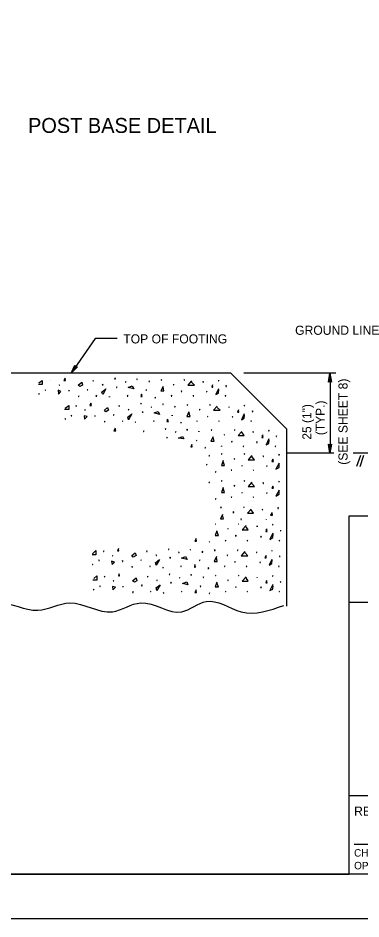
# Model space of a CAD drawing. Extents: x 637580 to 641008, y 294594 to 295782.
# Drawn here: x 638095.4 to 638210.3, y 294593.6 to 294895.4 of the extents above; entities that cross this region are included whole.
import ezdxf

# ---------------------------------------------------------------- set-up
doc = ezdxf.new("R2010")
doc.units = 0
for name, color, linetype in [('1', 7, 'Continuous'), ('2', 7, 'Continuous'), ('3', 7, 'Continuous'), ('PLT-BNDY', 7, 'Continuous')]:
    doc.layers.add(name, color=color, linetype=linetype)

# ---------------------------------------------------------------- blocks, each defined once
blk = doc.blocks.new('RARROW')
at = {"layer": '3'}
blk.add_lwpolyline([(-2.2695, 0.285), (-2.184875, 0.12075), (0, 0), (-2.2695, 0.285), (-2.38575, 0.384625), (0, 0), (-2.183125, -0.108), (-2.262875, -0.2705), (0, 0), (-2.38575, -0.379125), (-2.262875, -0.2705)], dxfattribs=at)

msp = doc.modelspace()

# ---------------------------------------------------------------- linework, layer by layer
at = {"layer": '1'}
for p, q in [((638210.18, 294748.88), (638208.8, 294745.13)), ((638211.18, 294748.88), (638209.93, 294745)), ((638206.31, 294608.63), (638206.31, 294728.63)), ((638206.31, 294728.63), (638406.31, 294728.63)), ((638406.31, 294699.63), (638206.31, 294699.63)), ((638206.31, 294635), (638406.31, 294635)), ((638207.99, 294618.68), (638281.87, 294618.68)), ((638406.31, 294608.63), (637620.31, 294608.63)), ((637620.31, 294608.63), (638206.31, 294608.63))]:
    msp.add_line(p, q, dxfattribs=at)
at = {"layer": '2'}
for p, q in [((638121.3, 294788), (638113.25, 294776.38)), ((638128.7, 294788), (638121.3, 294788)), ((638166.68, 294776.38), (637860.68, 294776.38)), ((638166.68, 294776.38), (638185.3, 294757.75)), ((638201.93, 294776.38), (638171.05, 294776.38)), ((638199.93, 294776.38), (638199.93, 294749.63)), ((638185.3, 294757.75), (638185.3, 294698.38)), ((638201.18, 294749.63), (638185.3, 294749.63)), ((638232.3, 294749.63), (638207.68, 294749.63))]:
    msp.add_line(p, q, dxfattribs=at)
for points in [[(638102.43, 294773.13), (638103.55, 294774), (638103.55, 294772.63), (638102.3, 294772.63)], [(638106.18, 294773.88), (638106.18, 294773.88), (638106.18, 294773.88), (638106.18, 294773.88)], [(638109.18, 294772.5), (638109.18, 294772.38), (638109.3, 294772.38), (638109.18, 294772.5)], [(638111.18, 294774.75), (638110.8, 294774), (638111.3, 294774), (638111.18, 294774.75)], [(638115.55, 294772.38), (638116.8, 294773.38), (638117.05, 294772.38), (638116.18, 294772), (638115.55, 294772.38)], [(638120.68, 294773.88), (638120.55, 294773.88), (638120.68, 294773.88), (638120.68, 294773.88)], [(638123.8, 294772.75), (638123.68, 294772.5), (638123.93, 294772.5), (638123.8, 294772.63)], [(638128.05, 294774.75), (638127.8, 294774.5), (638128.05, 294774.5), (638128.05, 294774.63)], [(638131.55, 294773.63), (638131.43, 294773.38), (638131.55, 294773.38), (638131.55, 294773.63)], [(638135.18, 294774.5), (638135.18, 294774.25), (638135.3, 294774.25), (638135.18, 294774.5)], [(638139.43, 294773.88), (638139.3, 294773.63), (638139.43, 294773.63), (638139.43, 294773.88)], [(638143.55, 294774.25), (638143.43, 294774.13), (638143.55, 294774.13), (638143.55, 294774.25)], [(638147.55, 294772.75), (638147.55, 294772.5), (638147.68, 294772.5), (638147.55, 294772.63)], [(638151.05, 294774.25), (638151.05, 294774.13), (638151.18, 294774.13), (638151.05, 294774.25)], [(638153.55, 294773.88), (638152.3, 294772.38), (638154.55, 294772.38), (638153.55, 294773.38)], [(638157.43, 294773.63), (638157.3, 294773.38), (638157.55, 294773.38), (638157.43, 294773.63)], [(638160.55, 294772.5), (638160.3, 294771.75), (638160.68, 294771.75), (638160.55, 294772.38)], [(638162.55, 294774.13), (638162.55, 294773.88), (638162.68, 294773.88), (638162.55, 294774)], [(638102.43, 294769.63), (638102.43, 294769.38), (638102.55, 294769.38), (638102.43, 294769.63)], [(638104.55, 294770.88), (638104.55, 294770.75), (638104.68, 294770.75), (638104.55, 294770.88)], [(638108.93, 294770.75), (638109.05, 294769.38), (638109.8, 294770.25), (638108.93, 294770.75)], [(638112.55, 294770.75), (638112.43, 294770.5), (638112.55, 294770.5), (638112.55, 294770.75)], [(638118.68, 294771), (638118.55, 294770.88), (638118.8, 294770.88), (638118.68, 294771)], [(638123.68, 294770.13), (638124.8, 294771.13), (638123.8, 294769.25), (638123.43, 294770.13)], [(638128.55, 294771.88), (638128.43, 294771.63), (638128.55, 294771.63), (638128.55, 294771.88)], [(638134.18, 294771.13), (638132.3, 294771.63), (638133.68, 294772.13), (638134.18, 294771.13)], [(638138.43, 294770.88), (638138.3, 294770.75), (638138.43, 294770.75), (638138.43, 294770.88)], [(638144.05, 294772), (638143.3, 294770.5), (638144.3, 294770.5), (638144.05, 294771.88)], [(638150.18, 294770.5), (638150.05, 294770.25), (638150.3, 294770.25), (638150.18, 294770.5)], [(638158.68, 294770.38), (638158.55, 294770.13), (638158.68, 294770.13), (638158.68, 294770.25)], [(638162.55, 294771.13), (638161.68, 294769.25), (638162.55, 294769.75), (638162.68, 294770.88)], [(638165.18, 294772.25), (638165.05, 294772), (638165.3, 294772), (638165.18, 294772.25)], [(638115.8, 294768.88), (638115.68, 294768.63), (638115.8, 294768.63), (638115.8, 294768.75)], [(638121.68, 294769), (638121.55, 294768.75), (638121.8, 294768.75), (638121.68, 294768.88)], [(638126.05, 294768.63), (638126.05, 294768.38), (638126.05, 294768.38), (638126.05, 294768.63)], [(638132.18, 294769), (638132.05, 294768.75), (638132.18, 294768.75), (638132.18, 294768.88)], [(638136.8, 294769.38), (638136.55, 294768.63), (638137.05, 294768.63), (638136.8, 294769.38)], [(638141.43, 294768.38), (638141.3, 294768.13), (638141.43, 294768.13), (638141.43, 294768.38)], [(638146.8, 294769), (638146.68, 294768.75), (638146.93, 294768.75), (638146.8, 294768.88)], [(638154.05, 294769), (638154.05, 294768.75), (638154.18, 294768.75), (638154.05, 294768.88)], [(638164.93, 294769), (638164.8, 294768.75), (638164.93, 294768.75), (638164.93, 294768.88)], [(638111.18, 294764.75), (638112.43, 294765.63), (638112.43, 294764.25), (638111.05, 294764.25)], [(638114.93, 294765.63), (638114.8, 294765.38), (638115.05, 294765.38), (638114.93, 294765.5)], [(638117.93, 294764.25), (638117.8, 294764), (638117.93, 294764), (638117.93, 294764.13)], [(638119.8, 294766.38), (638119.55, 294765.63), (638120.05, 294765.63), (638119.8, 294766.38)], [(638124.43, 294764), (638125.43, 294764.88), (638125.8, 294764), (638124.8, 294763.5), (638124.43, 294764)], [(638129.3, 294765.63), (638129.18, 294765.38), (638129.43, 294765.38), (638129.3, 294765.5)], [(638132.43, 294764.38), (638132.43, 294764.13), (638132.55, 294764.13), (638132.43, 294764.38)], [(638136.68, 294766.38), (638136.55, 294766.13), (638136.68, 294766.13), (638136.68, 294766.38)], [(638137.18, 294763.5), (638137.05, 294763.38), (638137.3, 294763.38), (638137.18, 294763.38)], [(638140.18, 294765.13), (638140.05, 294765), (638140.18, 294765), (638140.18, 294765.13)], [(638142.8, 294762.63), (638141.05, 294763.13), (638142.43, 294763.63), (638142.8, 294762.63)], [(638144.05, 294766.13), (638143.93, 294765.88), (638144.05, 294765.88), (638144.05, 294766.13)], [(638148.05, 294765.38), (638147.8, 294765.13), (638148.05, 294765.13), (638148.05, 294765.38)], [(638152.68, 294763.5), (638151.93, 294761.88), (638153.05, 294761.88), (638152.68, 294763.38)], [(638152.18, 294765.88), (638152.05, 294765.75), (638152.18, 294765.75), (638152.18, 294765.88)], [(638156.3, 294764.38), (638156.18, 294764.13), (638156.3, 294764.13), (638156.3, 294764.38)], [(638159.8, 294765.88), (638159.68, 294765.75), (638159.8, 294765.75), (638159.8, 294765.88)], [(638162.18, 294765.38), (638160.93, 294764), (638163.18, 294764), (638162.18, 294764.88)], [(638166.05, 294765.13), (638166.05, 294765), (638166.18, 294765), (638166.05, 294765.13)], [(638169.3, 294764.13), (638168.93, 294763.38), (638169.43, 294763.38), (638169.3, 294764)], [(638171.3, 294765.75), (638171.18, 294765.5), (638171.3, 294765.5), (638171.3, 294765.75)], [(638173.93, 294763.75), (638173.93, 294763.5), (638174.05, 294763.5), (638173.93, 294763.75)], [(638111.18, 294761.25), (638111.18, 294761), (638111.3, 294761), (638111.18, 294761.25)], [(638113.3, 294762.38), (638113.3, 294762.13), (638113.43, 294762.13), (638113.3, 294762.38)], [(638117.55, 294762.13), (638117.68, 294761), (638118.55, 294761.88), (638117.55, 294762.13)], [(638121.18, 294762.25), (638121.18, 294762), (638121.3, 294762), (638121.18, 294762.13)], [(638127.55, 294762.63), (638127.43, 294762.38), (638127.55, 294762.38), (638127.55, 294762.63)], [(638130.43, 294760.5), (638130.43, 294760.38), (638130.55, 294760.38), (638130.43, 294760.5)], [(638132.3, 294761.75), (638133.55, 294762.75), (638132.43, 294760.75), (638132.18, 294761.75)], [(638140.93, 294760.5), (638140.8, 294760.38), (638141.05, 294760.38), (638140.93, 294760.5)], [(638145.55, 294761), (638145.3, 294760.25), (638145.8, 294760.25), (638145.55, 294760.88)], [(638147.05, 294762.38), (638147.05, 294762.13), (638147.05, 294762.13), (638147.05, 294762.38)], [(638155.43, 294760.5), (638155.3, 294760.38), (638155.43, 294760.38), (638155.43, 294760.5)], [(638158.93, 294762), (638158.93, 294761.88), (638159.05, 294761.88), (638158.93, 294762)], [(638162.8, 294760.5), (638162.68, 294760.38), (638162.8, 294760.38), (638162.8, 294760.5)], [(638167.3, 294761.88), (638167.18, 294761.75), (638167.43, 294761.75), (638167.3, 294761.88)], [(638171.18, 294762.75), (638170.3, 294760.75), (638171.18, 294761.38), (638171.3, 294762.38)], [(638173.55, 294760.5), (638173.43, 294760.38), (638173.68, 294760.38), (638173.55, 294760.5)], [(638124.55, 294760.38), (638124.43, 294760.13), (638124.55, 294760.13), (638124.55, 294760.38)], [(638127.93, 294758), (638127.55, 294757.13), (638128.18, 294757.13), (638127.93, 294757.88)], [(638134.8, 294760.13), (638134.68, 294760), (638134.8, 294760), (638134.8, 294760.13)], [(638144.8, 294757.88), (638144.68, 294757.63), (638144.93, 294757.63), (638144.8, 294757.75)], [(638150.05, 294760), (638149.93, 294759.75), (638150.05, 294759.75), (638150.05, 294760)], [(638152.05, 294757.63), (638151.93, 294757.38), (638152.18, 294757.38), (638152.05, 294757.63)], [(638160.3, 294757.5), (638160.18, 294757.38), (638160.3, 294757.38), (638160.3, 294757.38)], [(638167.93, 294757.5), (638167.93, 294757.38), (638168.05, 294757.38), (638167.93, 294757.38)], [(638179.43, 294757.38), (638179.3, 294757.13), (638179.55, 294757.13), (638179.43, 294757.38)], [(638137.55, 294757.13), (638137.43, 294756.88), (638137.55, 294756.88), (638137.55, 294757.13)], [(638145.43, 294755), (638145.3, 294754.75), (638145.43, 294754.75), (638145.43, 294755)], [(638148.3, 294756.88), (638148.18, 294756.63), (638148.3, 294756.63), (638148.3, 294756.75)], [(638150.93, 294754.38), (638149.18, 294754.63), (638150.55, 294755.25), (638150.93, 294754.38)], [(638156.05, 294757), (638156.05, 294756.75), (638156.05, 294756.75), (638156.05, 294756.88)], [(638160.8, 294755.13), (638160.05, 294753.63), (638161.18, 294753.63), (638160.8, 294755)], [(638164.43, 294755.88), (638164.43, 294755.75), (638164.55, 294755.75), (638164.43, 294755.88)], [(638170.43, 294756.88), (638169.18, 294755.5), (638171.18, 294755.5), (638170.43, 294756.63)], [(638174.18, 294756.88), (638174.05, 294756.63), (638174.3, 294756.63), (638174.18, 294756.75)], [(638177.3, 294755.75), (638177.05, 294754.88), (638177.55, 294754.88), (638177.3, 294755.63)], [(638179.43, 294754.38), (638178.55, 294752.38), (638179.43, 294752.88), (638179.55, 294754)], [(638182.05, 294755.38), (638181.93, 294755.25), (638182.05, 294755.25), (638182.05, 294755.38)], [(638153.68, 294752.5), (638153.3, 294751.75), (638153.8, 294751.75), (638153.68, 294752.5)], [(638155.18, 294754), (638155.18, 294753.88), (638155.3, 294753.88), (638155.18, 294754)], [(638158.18, 294751.5), (638158.05, 294751.38), (638158.18, 294751.38), (638158.18, 294751.5)], [(638163.55, 294752.13), (638163.55, 294751.88), (638163.55, 294751.88), (638163.55, 294752)], [(638167.05, 294753.63), (638166.93, 294753.38), (638167.18, 294753.38), (638167.05, 294753.63)], [(638170.93, 294752.13), (638170.8, 294751.88), (638170.93, 294751.88), (638170.93, 294752)], [(638175.55, 294753.5), (638175.3, 294753.25), (638175.55, 294753.25), (638175.55, 294753.38)], [(638181.68, 294752.13), (638181.55, 294751.88), (638181.68, 294751.88), (638181.68, 294752)], [(638159.55, 294748.88), (638159.3, 294748.75), (638159.55, 294748.75), (638159.55, 294748.88)], [(638163.68, 294749.5), (638163.55, 294749.25), (638163.68, 294749.25), (638163.68, 294749.5)], [(638171.3, 294749.5), (638171.18, 294749.25), (638171.3, 294749.25), (638171.3, 294749.5)], [(638173.8, 294748.88), (638172.55, 294747.38), (638174.68, 294747.38), (638173.8, 294748.5)], [(638177.55, 294748.75), (638177.55, 294748.5), (638177.68, 294748.5), (638177.55, 294748.75)], [(638182.93, 294749.25), (638182.8, 294749), (638182.93, 294749), (638182.93, 294749.25)], [(638158.68, 294746), (638158.55, 294745.75), (638158.68, 294745.75), (638158.68, 294745.88)], [(638164.18, 294747.13), (638163.55, 294745.5), (638164.55, 294745.5), (638164.18, 294746.88)], [(638167.93, 294747.88), (638167.8, 294747.63), (638167.93, 294747.63), (638167.93, 294747.88)], [(638170.43, 294745.5), (638170.43, 294745.38), (638170.55, 294745.38), (638170.43, 294745.5)], [(638178.8, 294745.38), (638178.68, 294745.25), (638178.93, 294745.25), (638178.8, 294745.38)], [(638180.8, 294747.63), (638180.43, 294746.88), (638181.05, 294746.88), (638180.8, 294747.63)], [(638182.93, 294746.25), (638181.8, 294744.25), (638182.93, 294744.88), (638182.93, 294746)], [(638161.68, 294743.5), (638161.55, 294743.25), (638161.68, 294743.25), (638161.68, 294743.5)], [(638166.93, 294744), (638166.8, 294743.88), (638167.05, 294743.88), (638166.93, 294743.88)], [(638174.3, 294744), (638174.18, 294743.88), (638174.3, 294743.88), (638174.3, 294743.88)], [(638159.55, 294740), (638159.3, 294739.75), (638159.55, 294739.75), (638159.55, 294739.88)], [(638163.68, 294740.5), (638163.55, 294740.25), (638163.68, 294740.25), (638163.68, 294740.5)], [(638171.3, 294740.5), (638171.18, 294740.25), (638171.3, 294740.25), (638171.3, 294740.5)], [(638173.8, 294739.88), (638172.55, 294738.5), (638174.68, 294738.5), (638173.8, 294739.5)], [(638177.55, 294739.75), (638177.55, 294739.5), (638177.68, 294739.5), (638177.55, 294739.75)], [(638182.93, 294740.25), (638182.8, 294740), (638182.93, 294740), (638182.93, 294740.25)], [(638164.18, 294738.13), (638163.55, 294736.5), (638164.55, 294736.5), (638164.18, 294737.88)], [(638167.93, 294738.88), (638167.8, 294738.63), (638167.93, 294738.63), (638167.93, 294738.88)], [(638170.43, 294736.5), (638170.43, 294736.38), (638170.55, 294736.38), (638170.43, 294736.5)], [(638178.8, 294736.38), (638178.68, 294736.25), (638178.93, 294736.25), (638178.8, 294736.38)], [(638180.8, 294738.63), (638180.43, 294737.88), (638181.05, 294737.88), (638180.8, 294738.63)], [(638182.93, 294737.25), (638181.8, 294735.25), (638182.93, 294735.88), (638182.93, 294737)], [(638161.68, 294734.5), (638161.55, 294734.25), (638161.68, 294734.25), (638161.68, 294734.5)], [(638166.93, 294735), (638166.8, 294734.88), (638167.05, 294734.88), (638166.93, 294735)], [(638174.3, 294735), (638174.18, 294734.88), (638174.3, 294734.88), (638174.3, 294735)], [(638163.43, 294731.63), (638163.3, 294731.38), (638163.55, 294731.38), (638163.43, 294731.5)], [(638171.05, 294731.63), (638171.05, 294731.38), (638171.05, 294731.38), (638171.05, 294731.5)], [(638173.55, 294730.88), (638172.3, 294729.5), (638174.3, 294729.5), (638173.55, 294730.63)], [(638177.3, 294730.88), (638177.18, 294730.63), (638177.3, 294730.63), (638177.3, 294730.75)], [(638182.55, 294731.38), (638182.43, 294731.13), (638182.68, 294731.13), (638182.55, 294731.38)], [(638163.93, 294729.13), (638163.3, 294727.63), (638164.3, 294727.63), (638163.93, 294729)], [(638167.68, 294730), (638167.43, 294729.75), (638167.68, 294729.75), (638167.68, 294730)], [(638170.18, 294727.63), (638170.05, 294727.38), (638170.3, 294727.38), (638170.18, 294727.63)], [(638178.55, 294727.5), (638178.55, 294727.38), (638178.55, 294727.38), (638178.55, 294727.38)], [(638180.55, 294729.75), (638180.05, 294728.88), (638180.68, 294728.88), (638180.55, 294729.63)], [(638161.68, 294725.88), (638161.55, 294725.88), (638161.68, 294725.88), (638161.68, 294725.88)], [(638165.8, 294724.38), (638165.68, 294724.25), (638165.8, 294724.25), (638165.8, 294724.38)], [(638169.3, 294725.88), (638169.3, 294725.88), (638169.43, 294725.88), (638169.3, 294725.88)], [(638171.8, 294725.38), (638170.55, 294724), (638172.55, 294724), (638171.8, 294725)], [(638175.55, 294725.25), (638175.55, 294725), (638175.55, 294725), (638175.55, 294725.25)], [(638178.68, 294724.25), (638178.43, 294723.38), (638178.93, 294723.38), (638178.68, 294724.13)], [(638180.8, 294725.88), (638180.68, 294725.63), (638180.8, 294725.63), (638180.8, 294725.75)], [(638162.05, 294723.63), (638161.43, 294722), (638162.55, 294722), (638162.05, 294723.5)], [(638168.43, 294722.13), (638168.3, 294721.88), (638168.55, 294721.88), (638168.43, 294722.13)], [(638176.8, 294721.88), (638176.68, 294721.63), (638176.93, 294721.63), (638176.8, 294721.88)], [(638180.8, 294722.88), (638179.8, 294720.75), (638180.8, 294721.38), (638180.93, 294722.5)], [(638183.3, 294723.88), (638183.3, 294723.63), (638183.43, 294723.63), (638183.3, 294723.75)], [(638155.05, 294721), (638154.68, 294720.13), (638155.18, 294720.13), (638155.05, 294721)], [(638159.55, 294720), (638159.43, 294719.88), (638159.55, 294719.88), (638159.55, 294719.88)], [(638164.93, 294720.5), (638164.93, 294720.25), (638165.05, 294720.25), (638164.93, 294720.5)], [(638172.3, 294720.5), (638172.18, 294720.25), (638172.3, 294720.25), (638172.3, 294720.5)], [(638183.05, 294720.5), (638182.93, 294720.25), (638183.05, 294720.25), (638183.05, 294720.5)], [(638120.43, 294715.88), (638121.55, 294717), (638121.55, 294715.63), (638120.3, 294715.63)], [(638124.18, 294716.88), (638124.05, 294716.75), (638124.18, 294716.75), (638124.18, 294716.88)], [(638127.18, 294715.38), (638127.05, 294715.25), (638127.18, 294715.25), (638127.18, 294715.38)], [(638129.05, 294717.75), (638128.8, 294716.88), (638129.18, 294716.88), (638129.05, 294717.63)], [(638133.55, 294715.38), (638134.68, 294716.25), (638135.05, 294715.38), (638134.05, 294714.75), (638133.55, 294715.38)], [(638138.55, 294716.88), (638138.43, 294716.75), (638138.68, 294716.75), (638138.55, 294716.88)], [(638141.68, 294715.63), (638141.68, 294715.38), (638141.8, 294715.38), (638141.68, 294715.63)], [(638145.93, 294717.63), (638145.8, 294717.38), (638145.93, 294717.38), (638145.93, 294717.5)], [(638149.43, 294716.63), (638149.18, 294716.38), (638149.43, 294716.38), (638149.43, 294716.5)], [(638153.05, 294717.38), (638153.05, 294717.25), (638153.18, 294717.25), (638153.05, 294717.38)], [(638157.3, 294716.75), (638157.05, 294716.5), (638157.3, 294716.5), (638157.3, 294716.75)], [(638161.43, 294717.25), (638161.18, 294717), (638161.43, 294717), (638161.43, 294717.25)], [(638165.55, 294715.63), (638165.43, 294715.38), (638165.55, 294715.38), (638165.55, 294715.63)], [(638169.05, 294717.25), (638168.93, 294717), (638169.05, 294717), (638169.05, 294717.25)], [(638171.43, 294716.75), (638170.18, 294715.25), (638172.43, 294715.25), (638171.43, 294716.38)], [(638175.3, 294716.63), (638175.3, 294716.38), (638175.43, 294716.38), (638175.3, 294716.5)], [(638178.55, 294715.38), (638178.05, 294714.63), (638178.55, 294714.63), (638178.55, 294715.38)], [(638180.55, 294717), (638180.43, 294716.88), (638180.55, 294716.88), (638180.55, 294717)], [(638183.05, 294715.25), (638183.05, 294715), (638183.18, 294715), (638183.05, 294715.13)], [(638120.43, 294712.5), (638120.43, 294712.38), (638120.55, 294712.38), (638120.43, 294712.38)], [(638122.55, 294713.88), (638122.55, 294713.63), (638122.68, 294713.63), (638122.55, 294713.75)], [(638126.8, 294713.5), (638126.93, 294712.38), (638127.8, 294713.13), (638126.8, 294713.5)], [(638130.43, 294713.63), (638130.43, 294713.38), (638130.55, 294713.38), (638130.43, 294713.63)], [(638136.55, 294713.88), (638136.55, 294713.75), (638136.68, 294713.75), (638136.55, 294713.88)], [(638141.55, 294713), (638142.8, 294714), (638141.68, 294712.13), (638141.43, 294713)], [(638146.43, 294714.75), (638146.3, 294714.5), (638146.55, 294714.5), (638146.43, 294714.75)], [(638152.05, 294714), (638150.18, 294714.5), (638151.55, 294715), (638152.05, 294714)], [(638154.68, 294712.38), (638154.55, 294711.5), (638154.93, 294711.5), (638154.68, 294712.25)], [(638156.3, 294713.88), (638156.18, 294713.63), (638156.3, 294713.63), (638156.3, 294713.75)], [(638161.93, 294715), (638161.18, 294713.38), (638162.18, 294713.38), (638161.93, 294714.75)], [(638168.05, 294713.38), (638168.05, 294713.13), (638168.18, 294713.13), (638168.05, 294713.38)], [(638176.55, 294713.25), (638176.43, 294713), (638176.68, 294713), (638176.55, 294713.13)], [(638180.43, 294714), (638179.55, 294712.13), (638180.43, 294712.63), (638180.55, 294713.88)], [(638129.3, 294709.25), (638129.05, 294708.5), (638129.43, 294708.5), (638129.3, 294709.25)], [(638133.68, 294711.63), (638133.55, 294711.5), (638133.8, 294711.5), (638133.68, 294711.63)], [(638139.55, 294711.88), (638139.55, 294711.63), (638139.68, 294711.63), (638139.55, 294711.75)], [(638144.05, 294711.5), (638143.93, 294711.25), (638144.05, 294711.25), (638144.05, 294711.38)], [(638146.18, 294709.25), (638146.05, 294709), (638146.3, 294709), (638146.18, 294709.13)], [(638150.05, 294711.88), (638149.93, 294711.63), (638150.05, 294711.63), (638150.05, 294711.75)], [(638159.3, 294711.25), (638159.05, 294711), (638159.3, 294711), (638159.3, 294711.25)], [(638164.68, 294711.88), (638164.55, 294711.63), (638164.68, 294711.63), (638164.68, 294711.75)], [(638172.05, 294711.88), (638171.8, 294711.63), (638172.05, 294711.63), (638172.05, 294711.75)], [(638182.8, 294711.88), (638182.68, 294711.63), (638182.93, 294711.63), (638182.8, 294711.75)], [(638120.8, 294707.63), (638121.8, 294708.5), (638121.8, 294707.13), (638120.55, 294707.13)], [(638124.43, 294708.38), (638124.43, 294708.25), (638124.55, 294708.25), (638124.43, 294708.38)], [(638127.43, 294707), (638127.3, 294706.88), (638127.55, 294706.88), (638127.43, 294707)], [(638133.8, 294706.88), (638135.05, 294707.88), (638135.18, 294706.88), (638134.43, 294706.38), (638133.8, 294706.88)], [(638138.93, 294708.38), (638138.8, 294708.25), (638138.93, 294708.25), (638138.93, 294708.38)], [(638141.93, 294707.25), (638141.93, 294707), (638142.05, 294707), (638141.93, 294707.13)], [(638146.68, 294706.38), (638146.55, 294706.25), (638146.8, 294706.25), (638146.68, 294706.38)], [(638149.68, 294708), (638149.55, 294707.88), (638149.68, 294707.88), (638149.68, 294708)], [(638152.3, 294705.5), (638150.55, 294706), (638151.93, 294706.5), (638152.3, 294705.5)], [(638153.43, 294709), (638153.3, 294708.75), (638153.55, 294708.75), (638153.43, 294709)], [(638157.55, 294708.25), (638157.43, 294708), (638157.55, 294708), (638157.55, 294708.25)], [(638162.05, 294706.38), (638161.43, 294704.88), (638162.55, 294704.88), (638162.05, 294706.25)], [(638161.68, 294708.75), (638161.55, 294708.63), (638161.68, 294708.63), (638161.68, 294708.75)], [(638165.8, 294707.25), (638165.68, 294707), (638165.8, 294707), (638165.8, 294707.13)], [(638169.3, 294708.75), (638169.3, 294708.63), (638169.43, 294708.63), (638169.3, 294708.75)], [(638171.8, 294708.25), (638170.55, 294706.75), (638172.55, 294706.75), (638171.8, 294707.88)], [(638175.55, 294708), (638175.55, 294707.88), (638175.55, 294707.88), (638175.55, 294708)], [(638178.68, 294707), (638178.43, 294706.25), (638178.93, 294706.25), (638178.68, 294706.88)], [(638180.8, 294708.63), (638180.68, 294708.38), (638180.8, 294708.38), (638180.8, 294708.5)], [(638183.3, 294706.63), (638183.3, 294706.38), (638183.43, 294706.38), (638183.3, 294706.63)], [(638120.8, 294704.13), (638120.68, 294703.88), (638120.8, 294703.88), (638120.8, 294704.13)], [(638122.93, 294705.25), (638122.8, 294705), (638122.93, 294705), (638122.93, 294705.25)], [(638127.05, 294705), (638127.18, 294703.88), (638128.05, 294704.75), (638127.05, 294705)], [(638130.55, 294705.13), (638130.55, 294704.88), (638130.68, 294704.88), (638130.55, 294705)], [(638134.05, 294703.25), (638133.8, 294703), (638134.05, 294703), (638134.05, 294703.25)], [(638136.93, 294705.5), (638136.8, 294705.25), (638137.05, 294705.25), (638136.93, 294705.5)], [(638139.8, 294703.38), (638139.8, 294703.25), (638139.93, 294703.25), (638139.8, 294703.38)], [(638141.8, 294704.63), (638143.05, 294705.5), (638141.93, 294703.63), (638141.68, 294704.63)], [(638150.3, 294703.38), (638150.18, 294703.25), (638150.3, 294703.25), (638150.3, 294703.38)], [(638155.05, 294703.88), (638154.68, 294703), (638155.18, 294703), (638155.05, 294703.63)], [(638156.55, 294705.25), (638156.43, 294705), (638156.68, 294705), (638156.55, 294705.25)], [(638164.93, 294703.38), (638164.93, 294703.25), (638165.05, 294703.25), (638164.93, 294703.38)], [(638168.43, 294704.88), (638168.3, 294704.75), (638168.55, 294704.75), (638168.43, 294704.88)], [(638172.3, 294703.38), (638172.18, 294703.25), (638172.3, 294703.25), (638172.3, 294703.38)], [(638176.8, 294704.88), (638176.68, 294704.63), (638176.93, 294704.63), (638176.8, 294704.88)], [(638180.8, 294705.63), (638179.8, 294703.63), (638180.8, 294704.13), (638180.93, 294705.25)], [(638183.05, 294703.38), (638182.93, 294703.25), (638183.05, 294703.25), (638183.05, 294703.38)], [(638144.18, 294703), (638144.18, 294702.75), (638144.3, 294702.75), (638144.18, 294703)], [(638159.55, 294702.88), (638159.43, 294702.63), (638159.55, 294702.63), (638159.55, 294702.75)]]:
    msp.add_lwpolyline(points, dxfattribs=at)
msp.add_spline([(637860.55, 294697.38), (637873.43, 294700.75), (637882.43, 294696.5), (637895.3, 294699.5), (637907.93, 294696.5), (637922.43, 294699.5), (637935.05, 294697), (637947.05, 294700), (637959.55, 294697), (637971.3, 294699.5), (637985.55, 294696.5), (637995.05, 294700), (638007.55, 294697), (638018.3, 294700), (638032.55, 294697), (638042.43, 294699.5), (638056.68, 294696.5), (638064.8, 294699.5), (638078.18, 294697), (638088.93, 294699.5), (638102.05, 294697), (638112.8, 294699.5), (638127.05, 294696.5), (638136.55, 294699.5), (638150.3, 294696.5), (638158.43, 294700), (638170.18, 294696.5), (638184.43, 294698.63)], degree=3, dxfattribs=at)
at = {"layer": 'PLT-BNDY'}
msp.add_lwpolyline([(637580.31, 295187.63), (638421.31, 295187.63), (638421.31, 294593.63), (637580.31, 294593.63)], close=True, dxfattribs=at)

# ---------------------------------------------------------------- block references
at = {"layer": '2', "yscale": 1.3092961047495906}
for p, xscale, rotation in [((638113.25, 294776.38), 1.257434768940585, -124.2452503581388), ((638199.92, 294776.38), 1.2574347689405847, 89.99999999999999), ((638199.92, 294749.63), 1.2574347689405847, -90.00000000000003)]:
    msp.add_blockref('RARROW', p, dxfattribs=dict(at, xscale=xscale, rotation=rotation))

# ---------------------------------------------------------------- texts
at = {"layer": '1'}
for s, height, p in [('(SEE SHEET 8)', 3.033, (638205.8, 294745.75)), ('(TYP.)', 3, (638198.16, 294755.65)), ('25 (1")', 3, (638193.66, 294754.15))]:
    msp.add_text(s, height=height, rotation=90, dxfattribs=at).set_placement(p)
for s, height, p in [('RECOMMENDED', 3.048, (638207.99, 294628.2)), ('CHIEF, TRAFFIC ENGINEERING AND', 2.5, (638207.99, 294614.51)), ('OPERATIONS DIVISION', 2.5, (638207.99, 294610.26))]:
    msp.add_text(s, height=height, dxfattribs=at).set_placement(p)
at = {"layer": '2'}
msp.add_text('POST BASE DETAIL', height=5, dxfattribs=at).set_placement((638098.79, 294856.88))
at = {"layer": '3'}
for s, p in [('GROUND LINE', (638188.23, 294789.27)), ('TOP OF FOOTING', (638130.69, 294786.38))]:
    msp.add_text(s, height=3.0427, dxfattribs=at).set_placement(p)

doc.saveas('drawing.dxf')
